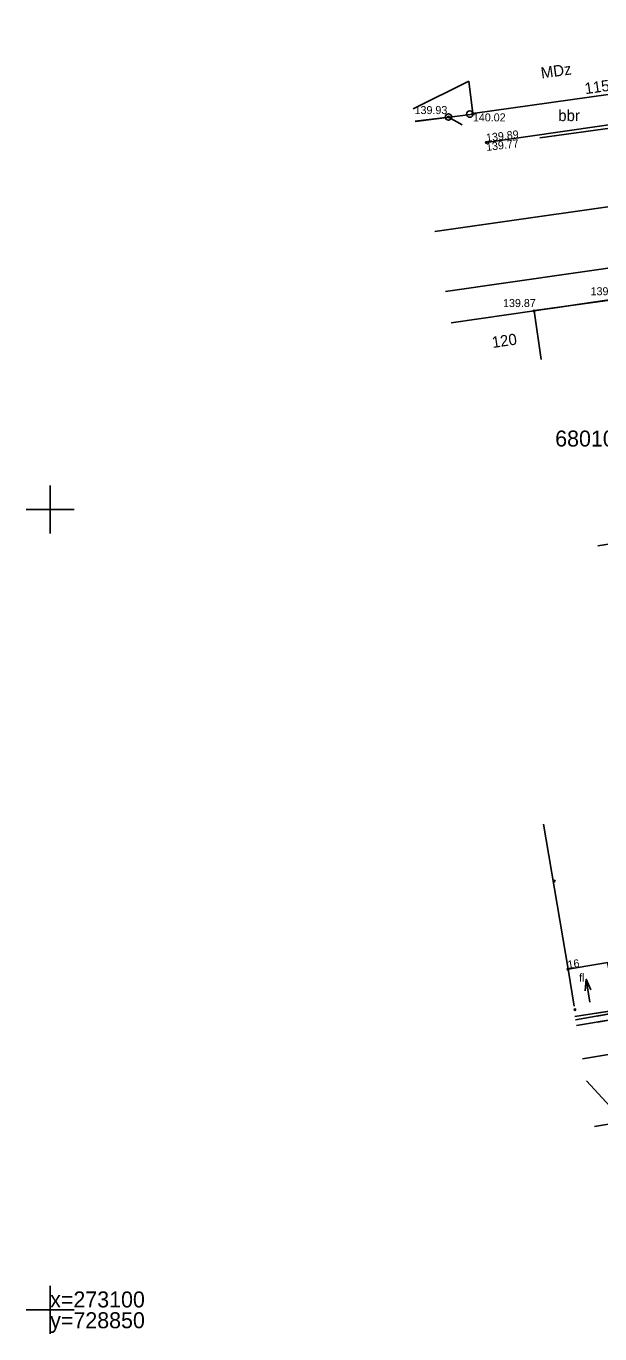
# Model space of a CAD drawing. Extents: x 728848 to 728956, y 273098 to 273185.
# Drawn here: x 728848.5 to 728884.3, y 273098.5 to 273180.2 of the extents above; entities that cross this region are included whole.
import ezdxf

# ---------------------------------------------------------------- set-up
doc = ezdxf.new("R2010")
doc.units = 0
for name, color, linetype in [('APGS_ACRL_####_####_#', 7, 'Continuous'), ('APGS_VADP_ZSPR_####_I', 7, 'Continuous'), ('BUVE_BDET_####_####_#', 7, 'Continuous'), ('BUVE_BDET_####_TKST_#', 7, 'Continuous'), ('BUVE_EKAS_####_####_#', 7, 'Continuous'), ('BUVE_EKAS_ADRS_TKST_#', 7, 'Continuous'), ('BUVE_EKAS_RAKS_TKST_#', 7, 'Continuous'), ('CELI_CAPM_####_####_#', 7, 'Continuous'), ('CELI_CMAL_####_####_#', 7, 'Continuous'), ('CELI_CSEG_####_TKST_#', 7, 'Continuous'), ('ELEK_VADP_ZSPR_####_I', 7, 'Continuous'), ('ELEK_VADV_ZSPR_####_#', 7, 'Continuous'), ('GEOD_ELEM_####_####_#', 7, 'Continuous'), ('GEOD_KORD_####_TKST_#', 7, 'Continuous'), ('NORB_ELEM_####_####_#', 7, 'Continuous'), ('NORB_ZOGS_ZSTP_####_#', 7, 'Continuous'), ('RELJ_AATZ_####_TKST_#', 7, 'Continuous'), ('RELJ_ELEM_####_####_#', 7, 'Continuous'), ('ROBZ_KADS_####_TKST_#', 7, 'Continuous'), ('ROBZ_UZMR_####_####_#', 7, 'Continuous'), ('SAKK_KKAN_####_####_#', 7, 'Continuous'), ('SKAN_VADP_PAST_####_#', 7, 'Continuous'), ('UDTK_VADP_UDEN_####_#', 7, 'Continuous')]:
    doc.layers.add(name, color=color, linetype=linetype)

msp = doc.modelspace()

# ---------------------------------------------------------------- linework, layer by layer
at = {"layer": 'APGS_ACRL_####_####_#'}
for points in [[(728882.8, 273118.116), (728887.366, 273118.92), (728896.816, 273120.42), (728897.026, 273120.224), (728897.316, 273118.953)], [(728884.152, 273118.354), (728887.366, 273118.92), (728896.816, 273120.42), (728897.026, 273120.224), (728897.316, 273118.953)]]:
    msp.add_lwpolyline(points, dxfattribs=at)
at = {"layer": 'APGS_VADP_ZSPR_####_I'}
for points in [[(728882.8, 273118.118), (728887.366, 273118.92), (728896.816, 273120.42), (728897.026, 273120.224), (728897.316, 273118.953)], [(728884.152, 273118.355), (728887.366, 273118.92), (728896.816, 273120.42), (728897.026, 273120.224), (728897.316, 273118.953)]]:
    msp.add_lwpolyline(points, dxfattribs=at)
at = {"layer": 'BUVE_BDET_####_####_#'}
for p, q in [((728882.332, 273121.28), (728882.723, 273118.976)), ((728883.474, 273120.653), (728883.689, 273119.225))]:
    msp.add_line(p, q, dxfattribs=at)
msp.add_lwpolyline([(728883.751, 273119.987), (728883.474, 273120.653), (728883.405, 273119.935)], dxfattribs=at)
at = {"layer": 'BUVE_EKAS_####_####_#'}
for p, q in [((728876.139, 273176.762), (728876.392, 273174.747)), ((728888.427, 273176.436), (728876.392, 273174.747)), ((728880.21, 273162.407), (728895.607, 273164.692)), ((728881.265, 273162.564), (728895.607, 273164.692)), ((728875.041, 273161.658), (728880.21, 273162.407)), ((728880.649, 273159.378), (728880.21, 273162.407)), ((728888.697, 273148.457), (728884.187, 273147.736)), ((728882.332, 273121.28), (728880.808, 273130.341)), ((728882.332, 273121.28), (728899.412, 273124.175)), ((728883.944, 273121.553), (728899.412, 273124.175))]:
    msp.add_line(p, q, dxfattribs=at)
at = {"layer": 'CELI_CAPM_####_####_#'}
for points in [[(728877.231, 273172.928), (728915.793, 273178.486), (728920.739, 273179.175), (728927.751, 273180.197)], [(728874.692, 273163.616), (728890.623, 273165.918), (728899.975, 273167.245), (728913.935, 273169.231), (728937.385, 273172.585), (728937.418, 273172.59)]]:
    msp.add_lwpolyline(points, dxfattribs=at)
at = {"layer": 'CELI_CMAL_####_####_#'}
for points in [[(728876.401, 273174.707), (728872.8, 273174.236)], [(728940.62, 273126.01), (728905.191, 273119.377), (728883.236, 273115.671)], [(728882.765, 273118.75), (728882.69, 273118.737)]]:
    msp.add_lwpolyline(points, dxfattribs=at)
at = {"layer": 'ELEK_VADP_ZSPR_####_I'}
for points in [[(728882.763, 273118.325), (728887.201, 273119.02), (728893.506, 273120.092), (728901.17, 273121.265), (728917.144, 273124.228), (728922.252, 273124.972), (728927.817, 273125.955)], [(728884.14, 273118.541), (728887.201, 273119.02), (728893.506, 273120.092), (728901.17, 273121.265), (728917.144, 273124.228), (728922.252, 273124.972), (728927.817, 273125.955)]]:
    msp.add_lwpolyline(points, dxfattribs=at)
at = {"layer": 'ELEK_VADV_ZSPR_####_#'}
for p, q in [((728880.569, 273173.213), (728911.092, 273177.457)), ((728872.659, 273175.03), (728876.139, 273176.762))]:
    msp.add_line(p, q, dxfattribs=at)
at = {"layer": 'GEOD_ELEM_####_####_#'}
for p, q in [((728850, 273151.5), (728850, 273150)), ((728848.5, 273150), (728850, 273150)), ((728850, 273150), (728850, 273148.5)), ((728850, 273150), (728851.5, 273150)), ((728850, 273101.5), (728850, 273100)), ((728848.5, 273100), (728850, 273100)), ((728850, 273100), (728850, 273098.5)), ((728850, 273100), (728851.5, 273100))]:
    msp.add_line(p, q, dxfattribs=at)
at = {"layer": 'NORB_ELEM_####_####_#'}
msp.add_line((728874.863, 273174.521), (728875.713, 273174.034), dxfattribs=at)
for centre in [(728874.863, 273174.521), (728876.199, 273174.707)]:
    msp.add_circle(centre, 0.202, dxfattribs=at)
at = {"layer": 'NORB_ZOGS_ZSTP_####_#'}
msp.add_lwpolyline([(728874.863, 273174.521), (728872.797, 273174.256)], dxfattribs=at)
at = {"layer": 'RELJ_ELEM_####_####_#'}
for centre in [(728876.392, 273174.747), (728874.863, 273174.521), (728877.231, 273172.928), (728880.21, 273162.407), (728881.477, 273126.791), (728882.332, 273121.28), (728882.765, 273118.75)]:
    msp.add_circle(centre, 0.05, dxfattribs=at)
at = {"layer": 'ROBZ_UZMR_####_####_#'}
msp.add_line((728895.601, 273164.553), (728880.25, 273162.441), dxfattribs=at)
at = {"layer": 'SAKK_KKAN_####_####_#'}
for points in [[(728882.864, 273117.761), (728887.446, 273118.532), (728897.906, 273120.141), (728908.778, 273121.814), (728946.269, 273127.973)], [(728884.177, 273117.982), (728887.446, 273118.532), (728897.906, 273120.141), (728908.778, 273121.814), (728934.266, 273126.001)]]:
    msp.add_lwpolyline(points, dxfattribs=at)
at = {"layer": 'SKAN_VADP_PAST_####_#'}
for points in [[(728874.023, 273167.371), (728904.501, 273171.712), (728935.767, 273176.034)], [(728883.987, 273111.458), (728886.872, 273111.928), (728884.797, 273121.698)]]:
    msp.add_lwpolyline(points, dxfattribs=at)
at = {"layer": 'UDTK_VADP_UDEN_####_#'}
msp.add_line((728883.481, 273114.299), (728887.486, 273109.955), dxfattribs=at)

# ---------------------------------------------------------------- texts
at = {"layer": 'BUVE_BDET_####_TKST_#'}
msp.add_text('fl.', height=0.5, dxfattribs=at).set_placement((728883.024, 273120.508))
at = {"layer": 'BUVE_EKAS_ADRS_TKST_#'}
for s, height, rotation, p in [('115', 0.7, 7.98875, (728883.422, 273175.946)), ('120', 0.7, 8.24858, (728877.632, 273160.09)), ('16', 0.5, 9.619, (728882.349, 273121.303))]:
    msp.add_text(s, height=height, rotation=rotation, dxfattribs=at).set_placement(p)
at = {"layer": 'BUVE_EKAS_RAKS_TKST_#'}
msp.add_text('MDz', height=0.7, rotation=7.98875, dxfattribs=at).set_placement((728880.685, 273176.92))
at = {"layer": 'CELI_CSEG_####_TKST_#'}
msp.add_text('bbr', height=0.7, dxfattribs=at).set_placement((728881.72, 273174.264))
at = {"layer": 'GEOD_KORD_####_TKST_#'}
for s, p in [('x=273100', (728850, 273100.15)), ('y=728850', (728850, 273098.85))]:
    msp.add_text(s, height=1, dxfattribs=at).set_placement(p)
at = {"layer": 'RELJ_AATZ_####_TKST_#'}
for s, p in [('139.93', (728872.751, 273174.704)), ('140.02', (728876.392, 273174.247)), ('139.80', (728883.741, 273163.385)), ('139.87', (728878.275, 273162.649))]:
    msp.add_text(s, height=0.5, dxfattribs=at).set_placement(p)
for s, p in [('139.89', (728877.246, 273172.971)), ('139.77', (728877.246, 273172.4))]:
    msp.add_text(s, height=0.5, rotation=6.62669, dxfattribs=at).set_placement(p)
at = {"layer": 'ROBZ_KADS_####_TKST_#'}
msp.add_text('68010040168', height=1, dxfattribs=at).set_placement((728881.532, 273153.934))

doc.saveas('drawing.dxf')
